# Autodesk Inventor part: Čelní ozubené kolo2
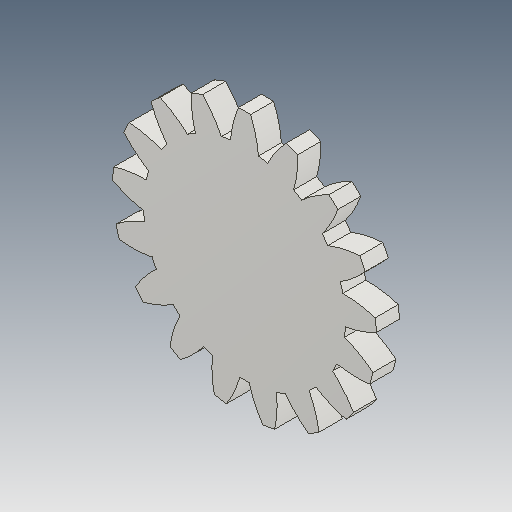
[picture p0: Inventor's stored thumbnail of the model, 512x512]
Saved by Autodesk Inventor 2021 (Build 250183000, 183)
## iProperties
Created: 2024-11
Part Number: Čelní ozubené kolo2
Material: Steel
Document SubType Name: Modeling
Designer: tatulinek
Categories: <?xml version="1.0" encoding="UTF-16"?> <MemberInstance><Categories><FamilyTemplate><FamilyTemplateParameter ValueType="xs:double" Id="1" ObjectReferenceKey="da
Density: 1 g/cm^3
Appearance: Steel
CustomPartVersion: 1
Author: tatulinek
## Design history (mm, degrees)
sketch "Sketch1"
  geometry: C1 r 114.747 at (0, 0)
  constraints: 1 centre point
  dimensions: "d0" = 229.494 diameter of C1 (= da_da)
extrude "Extrusion1" new body sketch "Sketch1" distance "d1" = 20 (= da_b); taper "d2" = 0 deg
workplane "Work Plane2"
sketch "Sketch2"
  geometry: C1 r 114.747 at (0, 0) reference; C2 r 102 at (0, 0)
  constraints: 1 centre point, 1 coincident
  dimensions: "d3" = 204 diameter of C2 (= da_d)
feature "Roztečný průměr" sketch "Sketch2" dims "d4" = 10, "d5" = 0
workplane "Work Plane8"
workplane "Work Plane9"
feature "Čelní ozubené kolo" dims "d5" = 0, "da_b" = 20, "da_d" = 204, "da_aw" = 174.747, "da_da" = 229.494, "da_df" = 175.51785, "da_dw" = 204.87579, angle "da_beta" = 0 deg, "da_lefttooth" = 0, "da_righttooth" = 0
body "Solid1"
body "Srf1"
other parameters: "d16" = 174.747 (= da_aw), "d17" = 0, "d34" = 1.848 (computed from da_z), "d39" = 0, "d41" = 0, "d43" = 174.747 (= da_aw), "d46" = 174.747 (= da_aw), "d47" = 0, "d48" = 0
